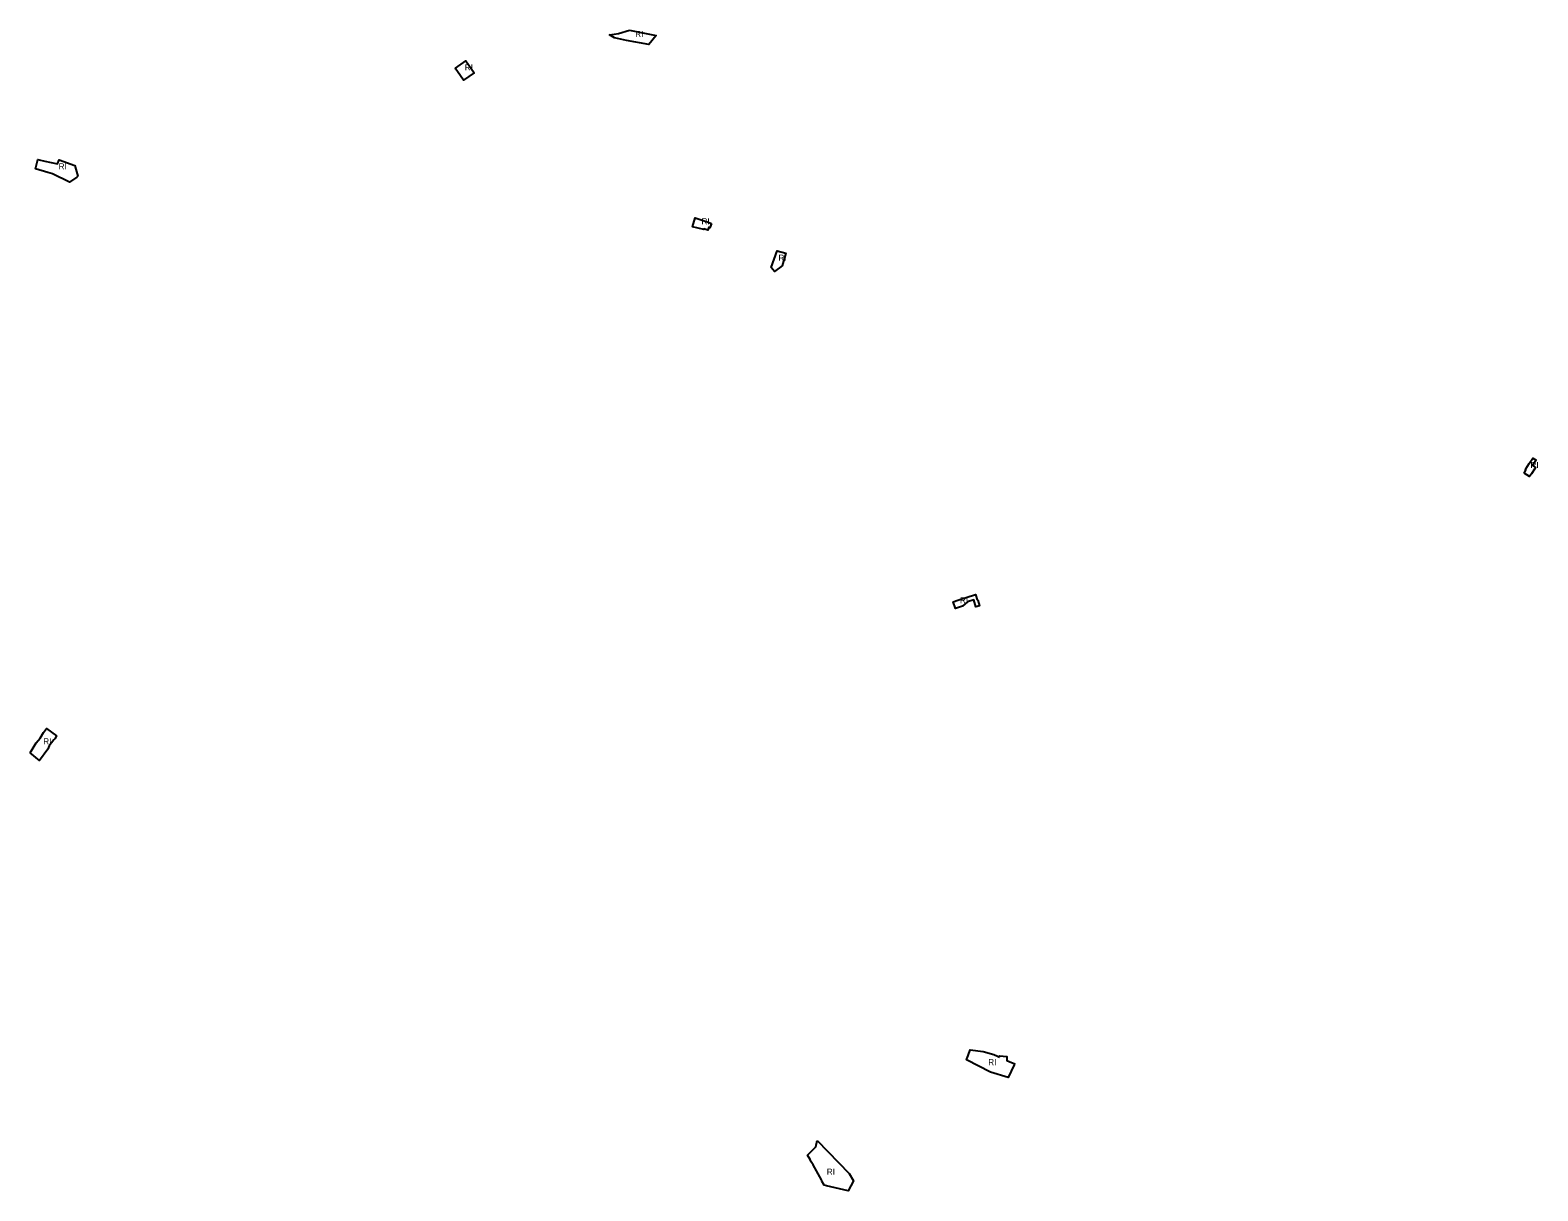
# Model space of a CAD drawing. Extents: x -477010 to -466219, y -1158799 to -1150161.
# Drawn here: x -473797 to -471577, y -1158436 to -1156726 of the extents above; entities that cross this region are included whole.
import ezdxf

# ---------------------------------------------------------------- set-up
doc = ezdxf.new("R2010")
doc.units = 0
doc.layers.add('19', color=7, linetype='Continuous')

msp = doc.modelspace()

# ---------------------------------------------------------------- linework, layer by layer
at = {"layer": '19'}
for points in [[(-472914.47, -1156726.41), (-472875.151, -1156734.281), (-472885.97, -1156747.46), (-472919.028, -1156741.815), (-472936.69, -1156737.51), (-472943.93, -1156733.17), (-472937.06, -1156732.32), (-472930.84, -1156731.55)], [(-473170.21, -1156783.85), (-473171.11, -1156782.55), (-473155.48, -1156771.76), (-473143.52, -1156789.08), (-473159.16, -1156799.87), (-473167.91, -1156787.19)], [(-473728.287, -1156942.863), (-473739.18, -1156950.08), (-473764.55, -1156937.91), (-473771.43, -1156935.95), (-473789.54, -1156930.78), (-473785.83, -1156916.85), (-473783.81, -1156917.31), (-473775.7, -1156919.14), (-473757.15, -1156923.32), (-473754.77, -1156917.28), (-473731.67, -1156925.53), (-473730.03, -1156931.27), (-473727.079, -1156941.608)], [(-472794.07, -1157010.91), (-472796.36, -1157017.28), (-472797.82, -1157016.76), (-472799.31, -1157020.9), (-472805.09, -1157018.82), (-472805.4, -1157020.14), (-472821.99, -1157015.825), (-472817.991, -1157002.727), (-472800.22, -1157008.7)], [(-472689.73, -1157073.37), (-472700.96, -1157081.64), (-472706.25, -1157076.16), (-472697.04, -1157051.22), (-472684.55, -1157054.88)], [(-471597.26, -1157378.6), (-471594.61, -1157374.46), (-471595.65, -1157373.78), (-471594.64, -1157372.25), (-471589.59, -1157364.6), (-471584.63, -1157356.47), (-471579.68, -1157359.59), (-471584.2, -1157366.71), (-471584.82, -1157367.66), (-471580.35, -1157370.53), (-471581.5, -1157372.28), (-471581.2, -1157372.48), (-471581.46, -1157373.03), (-471581.84, -1157372.8), (-471586.35, -1157379.79), (-471589.11, -1157383.95)], [(-472404.29, -1157560.45), (-472403.22, -1157563.8), (-472401.79, -1157565.69), (-472399.1, -1157574.1), (-472404.39, -1157575.79), (-472407.75, -1157565.24), (-472416.81, -1157568.14), (-472424.16, -1157574.69), (-472434.61, -1157578.04), (-472437.78, -1157568.13), (-472431, -1157565.96), (-472418.76, -1157562.05), (-472405.17, -1157557.7)], [(-473797.25, -1157790.52), (-473788.18, -1157776.1), (-473782.74, -1157769.21), (-473777.39, -1157760.9), (-473773.35, -1157754.64), (-473758.57, -1157765.75), (-473761.05, -1157770.22), (-473762.27, -1157771.73), (-473769.15, -1157780.23), (-473771.07, -1157785.13), (-473783.53, -1157801.81)], [(-472369.86, -1158238.75), (-472369.73, -1158236.96), (-472358.76, -1158237.76), (-472359.18, -1158243.48), (-472355.59, -1158245.07), (-472347.3, -1158248.75), (-472348.03, -1158250.26), (-472357.09, -1158268.96), (-472383.25, -1158260.95), (-472418.61, -1158242.71), (-472418.08, -1158241.34), (-472416.16, -1158236.51), (-472412.89, -1158227.82), (-472393.87, -1158230.6), (-472378.17, -1158235.01), (-472372.73, -1158237.48)], [(-472638.44, -1158361.41), (-472591.13, -1158410.03), (-472584.99, -1158420.74), (-472592.7, -1158435.67), (-472624.52, -1158428.27), (-472628.21, -1158427.41), (-472631.64, -1158421.66), (-472632.14, -1158419.49), (-472644.14, -1158397.55), (-472645.98, -1158394.44), (-472646.9, -1158392.88), (-472648.83, -1158389.61), (-472652.61, -1158383.21), (-472640.26, -1158370.82)]]:
    msp.add_lwpolyline(points, close=True, dxfattribs=at)

# ---------------------------------------------------------------- texts
for p in [(-472906.179, -1156736.485), (-473157.252, -1156785.811), (-473755.336, -1156931.575), (-472808.626, -1157012.401), (-472695.356, -1157065.961), (-471587.931, -1157371.217), (-472428.045, -1157570.491), (-473777.994, -1157778.215), (-472386.3826, -1158250.7018), (-472624.0826, -1158412.0078)]:
    msp.add_text('RI', height=9, dxfattribs=at).set_placement(p)

doc.saveas('drawing.dxf')
